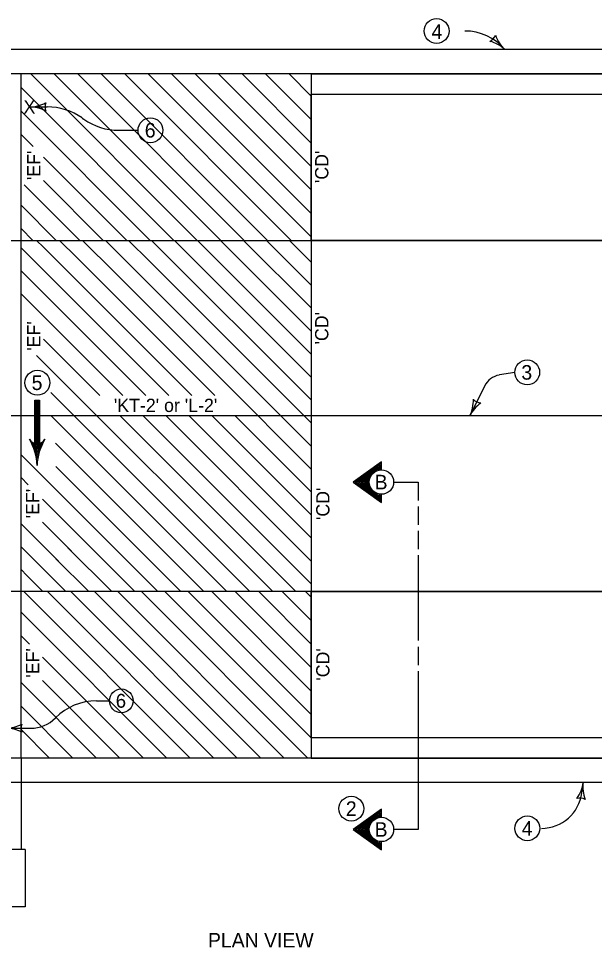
# Model space of a CAD drawing. Extents: x 10045 to 81668, y 6370 to 11018.
# Drawn here: x 10888 to 11617, y 6370 to 7544 of the extents above; entities that cross this region are included whole.
import ezdxf

# ---------------------------------------------------------------- set-up
doc = ezdxf.new("R2010")
doc.units = 0
for name, color, linetype in [('Alignment', 7, 'Continuous'), ('Default', 7, 'Continuous'), ('dsnStdLineWork', 7, 'Continuous')]:
    doc.layers.add(name, color=color, linetype=linetype)

msp = doc.modelspace()

# ---------------------------------------------------------------- linework, layer by layer
at = {"layer": 'Alignment'}
for p, q in [((11515.8, 7097), (11496.3, 7093.7)), ((11515.8, 7097), (11496.3, 7093.7)), ((11477.5, 7079.7), (11458.8, 7041.9)), ((11477.5, 7079.7), (11458.8, 7041.9)), ((10898.5, 6840.3), (10891.3, 6847.6)), ((10898.5, 6840.3), (10891.3, 6847.6)), ((12067.5, 6819.8), (10703.2, 6819.8)), ((12067.5, 6819.8), (10703.2, 6819.8)), ((11393.4, 6719.3), (11393.4, 6519.1)), ((11393.4, 6719.3), (11393.4, 6519.1)), ((10986.8, 6681.7), (11003.1, 6681.7)), ((10986.8, 6681.7), (11003.1, 6681.7)), ((10872.2, 6647.1), (10903.5, 6647.1)), ((10872.2, 6647.1), (10903.5, 6647.1)), ((11600.6, 6565.4), (11602.2, 6578.5)), ((11600.6, 6565.4), (11602.2, 6578.5))]:
    msp.add_line(p, q, dxfattribs=at)
for points in [[(11362.6, 6958.3), (11393.4, 6958.3), (11393.4, 6935.2)], [(11362.6, 6958.3), (11393.4, 6958.3), (11393.4, 6935.2)], [(11393.4, 6927.5), (11393.4, 6904.4)], [(11393.4, 6927.5), (11393.4, 6904.4)], [(11393.4, 6896.7), (11393.4, 6873.5)], [(11393.4, 6896.7), (11393.4, 6873.5)], [(11393.4, 6865.8), (11393.4, 6757.9)], [(11393.4, 6865.8), (11393.4, 6757.9)], [(11393.4, 6750.2), (11393.4, 6727)], [(11393.4, 6750.2), (11393.4, 6727)], [(11393.4, 6530.5), (11393.4, 6519.1), (11362.6, 6519.1)], [(11393.4, 6530.5), (11393.4, 6519.1), (11362.6, 6519.1)]]:
    msp.add_lwpolyline(points, dxfattribs=at)
for centre, radius, start, end in [((11452.5, 7461.8), 66.8, 40.5607, 90), ((11452.5, 7461.8), 66.8, 40.5607, 90), ((11500.5, 7068.3), 25.7, 99.5323, 153.7542), ((11500.5, 7068.3), 25.7, 99.5323, 153.7542), ((10986.8, 6608.3), 73.4, 90, 135), ((10986.8, 6608.3), 73.4, 90, 135), ((10903.5, 6691.2), 44.1, 270, 315), ((10903.5, 6691.2), 44.1, 270, 315), ((11549.6, 6571.9), 51.4, 270, 352.7713), ((11549.6, 6571.9), 51.4, 270, 352.7713)]:
    msp.add_arc(centre, radius, start, end, dxfattribs=at)
at = {"layer": 'Default'}
msp.add_line((11628.3, 7474.4), (10703.2, 7474.4), dxfattribs=at)
msp.add_line((11628.3, 7474.4), (10703.2, 7474.4), dxfattribs=at)
at = {"layer": 'dsnStdLineWork'}
for p, q in [((11591.3, 7505.2), (10703.2, 7505.2)), ((11591.3, 7505.2), (10703.2, 7505.2)), ((12004.1, 7505.2), (11591.3, 7505.2)), ((12004.1, 7505.2), (11591.3, 7505.2)), ((10891.3, 7263.9), (10891.3, 7474.4)), ((10891.3, 7263.9), (10891.3, 7474.4)), ((11114.1, 7263.9), (10903.6, 7474.4)), ((11114.1, 7263.9), (10903.6, 7474.4)), ((11143.8, 7263.9), (10933.3, 7474.4)), ((11143.8, 7263.9), (10933.3, 7474.4)), ((11173.5, 7263.9), (10963, 7474.4)), ((11173.5, 7263.9), (10963, 7474.4)), ((11203.2, 7263.9), (10992.7, 7474.4)), ((11203.2, 7263.9), (10992.7, 7474.4)), ((11232.9, 7263.9), (11022.4, 7474.4)), ((11232.9, 7263.9), (11022.4, 7474.4)), ((11258.2, 7268.2), (11052.1, 7474.4)), ((11258.2, 7268.2), (11052.1, 7474.4)), ((11258.2, 7297.9), (11081.8, 7474.4)), ((11258.2, 7297.9), (11081.8, 7474.4)), ((11258.2, 7327.6), (11111.5, 7474.4)), ((11258.2, 7327.6), (11111.5, 7474.4)), ((11258.2, 7357.3), (11141.2, 7474.4)), ((11258.2, 7357.3), (11141.2, 7474.4)), ((11258.2, 7387), (11170.9, 7474.4)), ((11258.2, 7387), (11170.9, 7474.4)), ((11258.2, 7416.7), (11200.6, 7474.4)), ((11258.2, 7416.7), (11200.6, 7474.4)), ((11258.2, 7446.4), (11230.3, 7474.4)), ((11258.2, 7446.4), (11230.3, 7474.4)), ((11628.3, 7474.4), (11258.2, 7474.4)), ((11258.2, 7474.4), (11628.3, 7474.4)), ((11258.2, 7474.4), (11258.2, 6819.8)), ((11628.3, 7474.4), (11258.2, 7474.4)), ((11258.2, 7474.4), (11628.3, 7474.4)), ((11258.2, 7474.4), (11258.2, 6819.8)), ((11084.4, 7263.9), (10891.3, 7457)), ((11084.4, 7263.9), (10891.3, 7457)), ((10891.3, 7263.9), (10891.3, 7448.9)), ((10891.3, 7263.9), (10891.3, 7448.9)), ((11258.2, 7263.9), (11258.2, 7448.9)), ((11258.2, 7263.9), (11258.2, 7448.9)), ((11258.2, 7448.9), (11628.3, 7448.9)), ((11258.2, 7263.9), (11258.2, 7448.9)), ((11258.2, 7263.9), (11258.2, 7448.9)), ((11258.2, 7448.9), (11628.3, 7448.9)), ((11054.7, 7263.9), (10891.3, 7427.3)), ((11054.7, 7263.9), (10891.3, 7427.3)), ((10901.6, 7432.6), (10924.3, 7432.6)), ((10901.6, 7432.6), (10924.3, 7432.6)), ((10968.5, 7418.6), (10970.8, 7417)), ((10968.5, 7418.6), (10970.8, 7417)), ((11015, 7403.1), (11039.2, 7403.1)), ((11015, 7403.1), (11039.2, 7403.1)), ((10906.5, 7382.4), (10891.3, 7397.6)), ((10906.5, 7382.4), (10891.3, 7397.6)), ((11025, 7263.9), (10919.7, 7369.2)), ((11025, 7263.9), (10919.7, 7369.2)), ((10965.6, 7263.9), (10895.2, 7334.2)), ((10965.6, 7263.9), (10895.2, 7334.2)), ((10995.3, 7263.9), (10919.7, 7339.5)), ((10995.3, 7263.9), (10919.7, 7339.5)), ((10935.9, 7263.9), (10891.3, 7308.5)), ((10935.9, 7263.9), (10891.3, 7308.5)), ((10906.2, 7263.9), (10891.3, 7278.8)), ((10906.2, 7263.9), (10891.3, 7278.8)), ((10703.2, 7263.9), (12114.2, 7263.9)), ((10703.2, 7263.9), (12114.2, 7263.9)), ((10891.3, 6819.8), (10891.3, 7263.9)), ((10891.3, 6819.8), (10891.3, 7263.9)), ((10919.6, 7255.4), (10911, 7263.9)), ((10919.6, 7255.4), (10911, 7263.9)), ((10961.9, 7242.1), (10940.1, 7263.9)), ((10961.9, 7242.1), (10940.1, 7263.9)), ((11010.3, 7222.8), (10969.2, 7263.9)), ((11010.3, 7222.8), (10969.2, 7263.9)), ((11036.2, 7225.9), (10998.3, 7263.9)), ((11036.2, 7225.9), (10998.3, 7263.9)), ((11053.6, 7237.6), (11027.3, 7263.9)), ((11053.6, 7237.6), (11027.3, 7263.9)), ((11258.2, 7062.1), (11056.4, 7263.9)), ((11258.2, 7062.1), (11056.4, 7263.9)), ((11258.2, 7091.1), (11085.5, 7263.9)), ((11258.2, 7091.1), (11085.5, 7263.9)), ((11258.2, 7120.2), (11114.6, 7263.9)), ((11258.2, 7120.2), (11114.6, 7263.9)), ((11258.2, 7149.3), (11143.6, 7263.9)), ((11258.2, 7149.3), (11143.6, 7263.9)), ((11258.2, 7178.4), (11172.7, 7263.9)), ((11258.2, 7178.4), (11172.7, 7263.9)), ((11258.2, 7207.4), (11201.8, 7263.9)), ((11258.2, 7207.4), (11201.8, 7263.9)), ((11258.2, 7236.5), (11230.9, 7263.9)), ((11258.2, 7236.5), (11230.9, 7263.9)), ((11628.3, 7263.9), (11258.2, 7263.9)), ((11258.2, 7263.9), (11258.2, 6819.8)), ((11628.3, 7263.9), (11258.2, 7263.9)), ((11628.3, 7263.9), (11258.2, 7263.9)), ((11258.2, 7263.9), (11258.2, 6819.8)), ((11628.3, 7263.9), (11258.2, 7263.9)), ((11078.2, 7067.7), (10891.3, 7254.6)), ((11078.2, 7067.7), (10891.3, 7254.6)), ((11107.2, 7067.7), (10919.6, 7255.4)), ((11107.2, 7067.7), (10919.6, 7255.4)), ((11136.3, 7067.7), (10961.9, 7242.1)), ((11136.3, 7067.7), (10961.9, 7242.1)), ((11258.2, 7033), (11053.6, 7237.6)), ((11258.2, 7033), (11053.6, 7237.6)), ((11049.1, 7067.7), (10891.3, 7225.5)), ((11049.1, 7067.7), (10891.3, 7225.5)), ((11010.3, 7222.8), (11017.1, 7216)), ((11144.7, 7088.4), (11010.3, 7222.8)), ((11010.3, 7222.8), (11017.1, 7216)), ((11144.7, 7088.4), (11010.3, 7222.8)), ((11258.2, 7003.9), (11036.2, 7225.9)), ((11258.2, 7003.9), (11036.2, 7225.9)), ((11020, 7067.7), (10891.3, 7196.4)), ((11020, 7067.7), (10891.3, 7196.4)), ((11258.7, 7154), (11258.2, 7154.4)), ((11258.7, 7154), (11258.2, 7154.4)), ((10990.9, 7067.7), (10919.7, 7138.9)), ((10990.9, 7067.7), (10919.7, 7138.9)), ((11209.8, 6819.8), (10911, 7118.5)), ((11209.8, 6819.8), (10911, 7118.5)), ((11258.2, 6974.8), (11144.7, 7088.4)), ((11258.2, 6974.8), (11144.7, 7088.4)), ((11180.7, 6819.8), (10929, 7071.5)), ((11180.7, 6819.8), (10929, 7071.5)), ((10911.7, 7007.2), (10911.7, 7061.7)), ((10911.7, 7007.2), (10911.7, 7061.7)), ((11628.3, 7041.9), (10112, 7041.9)), ((11628.3, 7041.9), (10112, 7041.9)), ((11151.6, 6819.8), (10929.6, 7041.9)), ((11151.6, 6819.8), (10929.6, 7041.9)), ((11169.4, 6889.3), (11016.8, 7041.9)), ((11169.4, 6889.3), (11016.8, 7041.9)), ((11183.9, 6903.8), (11045.9, 7041.9)), ((11183.9, 6903.8), (11045.9, 7041.9)), ((11258.2, 6858.5), (11074.9, 7041.9)), ((11258.2, 6858.5), (11074.9, 7041.9)), ((11258.2, 6887.6), (11104, 7041.9)), ((11258.2, 6887.6), (11104, 7041.9)), ((11258.2, 6916.7), (11133.1, 7041.9)), ((11258.2, 6916.7), (11133.1, 7041.9)), ((11258.2, 6945.8), (11162.2, 7041.9)), ((11258.2, 6945.8), (11162.2, 7041.9)), ((10908.4, 7007.3), (10908.4, 7007.3)), ((10908.4, 7007.3), (10908.4, 7007.3)), ((10914.7, 7007.3), (10914.7, 7007.3)), ((10914.7, 7007.3), (10914.7, 7007.3)), ((11122.5, 6819.8), (10935, 7007.3)), ((11122.5, 6819.8), (10935, 7007.3)), ((11006.1, 6878.1), (10891.3, 6992.9)), ((11006.1, 6878.1), (10891.3, 6992.9)), ((11022.6, 6890.7), (10935.4, 6977.8)), ((11022.6, 6890.7), (10935.4, 6977.8)), ((10900.4, 6954.8), (10891.3, 6963.9)), ((10900.4, 6954.8), (10891.3, 6963.9)), ((10977.6, 6877.5), (10918.4, 6936.7)), ((10977.6, 6877.5), (10918.4, 6936.7)), ((10938.7, 6858.3), (10891.3, 6905.7)), ((10938.7, 6858.3), (10891.3, 6905.7)), ((10955.1, 6870.9), (10918.4, 6907.6)), ((10955.1, 6870.9), (10918.4, 6907.6)), ((11093.5, 6819.8), (11018.4, 6894.8)), ((11093.5, 6819.8), (11018.4, 6894.8)), ((11258.2, 6829.5), (11183.9, 6903.8)), ((11258.2, 6829.5), (11183.9, 6903.8)), ((11238.8, 6819.8), (11169.4, 6889.3)), ((11238.8, 6819.8), (11169.4, 6889.3)), ((10923.2, 6844.7), (10891.3, 6876.6)), ((10923.2, 6844.7), (10891.3, 6876.6)), ((11006.2, 6819.8), (10950.7, 6875.3)), ((11006.2, 6819.8), (10950.7, 6875.3)), ((11035.3, 6819.8), (10977.6, 6877.5)), ((11035.3, 6819.8), (10977.6, 6877.5)), ((11064.4, 6819.8), (11006.1, 6878.1)), ((11064.4, 6819.8), (11006.1, 6878.1)), ((10977.2, 6819.8), (10935.5, 6861.4)), ((10977.2, 6819.8), (10935.5, 6861.4)), ((10919, 6819.8), (10898.5, 6840.3)), ((10919, 6819.8), (10898.5, 6840.3)), ((10948.1, 6819.8), (10923.2, 6844.7)), ((10948.1, 6819.8), (10923.2, 6844.7)), ((10891.3, 6609.3), (10891.3, 6819.8)), ((10891.3, 6609.3), (10891.3, 6819.8)), ((11105.4, 6609.3), (10895, 6819.8)), ((11105.4, 6609.3), (10895, 6819.8)), ((11135.1, 6609.3), (10924.7, 6819.8)), ((11135.1, 6609.3), (10924.7, 6819.8)), ((11164.8, 6609.3), (10954.4, 6819.8)), ((11164.8, 6609.3), (10954.4, 6819.8)), ((11194.5, 6609.3), (10984.1, 6819.8)), ((11194.5, 6609.3), (10984.1, 6819.8)), ((11224.2, 6609.3), (11013.8, 6819.8)), ((11224.2, 6609.3), (11013.8, 6819.8)), ((11253.9, 6609.3), (11043.5, 6819.8)), ((11253.9, 6609.3), (11043.5, 6819.8)), ((11258.2, 6634.8), (11073.1, 6819.8)), ((11258.2, 6634.8), (11073.1, 6819.8)), ((11258.2, 6664.4), (11102.8, 6819.8)), ((11258.2, 6664.4), (11102.8, 6819.8)), ((11258.2, 6694.1), (11132.5, 6819.8)), ((11258.2, 6694.1), (11132.5, 6819.8)), ((11258.2, 6723.8), (11162.2, 6819.8)), ((11258.2, 6723.8), (11162.2, 6819.8)), ((11258.2, 6753.5), (11191.9, 6819.8)), ((11258.2, 6753.5), (11191.9, 6819.8)), ((11258.2, 6783.2), (11221.6, 6819.8)), ((11258.2, 6783.2), (11221.6, 6819.8)), ((11258.2, 6812.9), (11251.3, 6819.8)), ((11258.2, 6812.9), (11251.3, 6819.8)), ((11258.2, 6819.8), (11258.2, 6634.8)), ((11258.2, 6819.8), (11258.2, 6634.8)), ((11258.2, 6819.8), (11258.2, 6609.3)), ((11258.2, 6634.8), (11258.2, 6819.8)), ((11258.2, 6819.8), (11628.3, 6819.8)), ((11258.2, 6819.8), (11628.3, 6819.8)), ((11258.2, 6819.8), (11258.2, 6634.8)), ((11258.2, 6819.8), (11258.2, 6634.8)), ((11258.2, 6819.8), (11258.2, 6609.3)), ((11258.2, 6634.8), (11258.2, 6819.8)), ((11258.2, 6819.8), (11628.3, 6819.8)), ((11258.2, 6819.8), (11628.3, 6819.8)), ((11075.7, 6609.3), (10891.3, 6793.8)), ((11075.7, 6609.3), (10891.3, 6793.8)), ((10902.1, 6753.3), (10891.3, 6764.1)), ((10902.1, 6753.3), (10891.3, 6764.1)), ((11046, 6609.3), (10918.4, 6736.9)), ((11046, 6609.3), (10918.4, 6736.9)), ((11016.3, 6609.3), (10918.4, 6707.3)), ((11016.3, 6609.3), (10918.4, 6707.3)), ((10986.6, 6609.3), (10891.3, 6704.7)), ((10986.6, 6609.3), (10891.3, 6704.7)), ((10956.9, 6609.3), (10891.3, 6675)), ((10956.9, 6609.3), (10891.3, 6675)), ((10927.2, 6609.3), (10891.3, 6645.3)), ((10927.2, 6609.3), (10891.3, 6645.3)), ((11628.3, 6634.8), (11258.2, 6634.8)), ((11628.3, 6634.8), (11258.2, 6634.8)), ((11628.3, 6609.3), (10703.2, 6609.3)), ((11628.3, 6609.3), (10703.2, 6609.3)), ((10891.3, 6609.3), (10891.3, 6493.6)), ((10891.3, 6609.3), (10891.3, 6493.6)), ((11591.3, 6578.5), (10703.2, 6578.5)), ((11591.3, 6578.5), (10703.2, 6578.5)), ((11918.6, 6578.5), (11591.3, 6578.5)), ((11918.6, 6578.5), (11591.3, 6578.5)), ((10896.4, 6493.6), (10880, 6493.6)), ((10896.4, 6493.6), (10880, 6493.6)), ((10896.4, 6493.6), (10896.4, 6421.2)), ((10896.4, 6493.6), (10896.4, 6421.2)), ((10896.4, 6421.2), (10880, 6421.2)), ((10896.4, 6421.2), (10880, 6421.2))]:
    msp.add_line(p, q, dxfattribs=at)
for points in [[(11628.3, 7456.6), (11628.3, 7456.6), (11628.3, 7474.4), (11258.2, 7474.4), (11258.2, 7448.9), (11628.3, 7448.9)], [(11628.3, 7456.6), (11628.3, 7456.6), (11628.3, 7474.4), (11258.2, 7474.4), (11258.2, 7448.9), (11628.3, 7448.9)], [(11628.3, 6627.1), (11628.3, 6634.8), (11258.2, 6634.8), (11258.2, 6609.3), (11628.3, 6609.3), (11628.3, 6627.1)], [(11628.3, 6627.1), (11628.3, 6634.8), (11258.2, 6634.8), (11258.2, 6609.3), (11628.3, 6609.3), (11628.3, 6627.1)]]:
    msp.add_lwpolyline(points, close=True, dxfattribs=at)
for points in [[(10891.3, 7263.9), (10891.3, 7263.9)], [(10891.3, 7263.9), (10891.3, 7263.9)], [(10908.6, 7007.3), (10908.6, 7061.7), (10914.7, 7061.7), (10914.7, 7007.3), (10909.5, 7007.5), (10909.3, 7061), (10914.2, 7060.9), (10914, 7008.5), (10910.3, 7008.3), (10910.1, 7060.2), (10913.3, 7060.1), (10913.3, 7009.2), (10911, 7009), (10910.8, 7059.6), (10912.6, 7059.6), (10912.5, 7009.8)], [(10908.6, 7007.3), (10908.6, 7061.7), (10914.7, 7061.7), (10914.7, 7007.3), (10909.5, 7007.5), (10909.3, 7061), (10914.2, 7060.9), (10914, 7008.5), (10910.3, 7008.3), (10910.1, 7060.2), (10913.3, 7060.1), (10913.3, 7009.2), (10911, 7009), (10910.8, 7059.6), (10912.6, 7059.6), (10912.5, 7009.8)], [(10904.6, 7008.7), (10908.2, 7006.4), (10913.6, 7006.2), (10918.3, 7008.1), (10915, 7000.1), (10912.3, 6990.7), (10911.6, 6988), (10910.3, 6994.8), (10906.9, 7004.7), (10905.3, 7007.7), (10916.8, 7006.6), (10911.8, 6992.1), (10907.6, 7006.2), (10915.5, 7005.7), (10911.8, 6995.7), (10909.5, 7004.9), (10914.1, 7005.3), (10912, 6998.9), (10910.7, 7003.8), (10912.9, 7004), (10912.2, 7001.7)], [(10904.6, 7008.7), (10908.2, 7006.4), (10913.6, 7006.2), (10918.3, 7008.1), (10915, 7000.1), (10912.3, 6990.7), (10911.6, 6988), (10910.3, 6994.8), (10906.9, 7004.7), (10905.3, 7007.7), (10916.8, 7006.6), (10911.8, 6992.1), (10907.6, 7006.2), (10915.5, 7005.7), (10911.8, 6995.7), (10909.5, 7004.9), (10914.1, 7005.3), (10912, 6998.9), (10910.7, 7003.8), (10912.9, 7004), (10912.2, 7001.7)], [(11347.2, 6973.7), (11347.2, 6984), (11311.2, 6958.3), (11347.2, 6932.6), (11347.2, 6942.9)], [(11347.2, 6973.7), (11347.2, 6984), (11311.2, 6958.3), (11347.2, 6932.6), (11347.2, 6942.9)], [(11346.2, 6941.9), (11346.3, 6934.5), (11313.1, 6958.3), (11346.3, 6982.4), (11346.1, 6974.5), (11344.7, 6974.1), (11345.3, 6979.8), (11315.3, 6958.3), (11345.3, 6936.6), (11344.9, 6942.1), (11343.9, 6942.3), (11343.9, 6938.6), (11317.3, 6958.4), (11344, 6977.2), (11343.5, 6974), (11342.3, 6973.7), (11342.5, 6974.8), (11319.6, 6958.1), (11342.8, 6940.6), (11341.7, 6942.5), (11321.6, 6958), (11333.9, 6967.7), (11333.2, 6965.9), (11323.7, 6957.9), (11332.8, 6950.9), (11332, 6952.8), (11325.6, 6957.6), (11332, 6963.1), (11331.4, 6960.7), (11327.3, 6957.6), (11331.4, 6954.3), (11331.2, 6956), (11328.8, 6957.5), (11331.1, 6958.9), (11331, 6957.4), (11330.2, 6957.5)], [(11346.2, 6941.9), (11346.3, 6934.5), (11313.1, 6958.3), (11346.3, 6982.4), (11346.1, 6974.5), (11344.7, 6974.1), (11345.3, 6979.8), (11315.3, 6958.3), (11345.3, 6936.6), (11344.9, 6942.1), (11343.9, 6942.3), (11343.9, 6938.6), (11317.3, 6958.4), (11344, 6977.2), (11343.5, 6974), (11342.3, 6973.7), (11342.5, 6974.8), (11319.6, 6958.1), (11342.8, 6940.6), (11341.7, 6942.5), (11321.6, 6958), (11333.9, 6967.7), (11333.2, 6965.9), (11323.7, 6957.9), (11332.8, 6950.9), (11332, 6952.8), (11325.6, 6957.6), (11332, 6963.1), (11331.4, 6960.7), (11327.3, 6957.6), (11331.4, 6954.3), (11331.2, 6956), (11328.8, 6957.5), (11331.1, 6958.9), (11331, 6957.4), (11330.2, 6957.5)], [(10891.3, 6819.8), (10891.3, 6819.8)], [(10891.3, 6819.8), (10891.3, 6819.8)], [(11347.2, 6534.5), (11347.2, 6544.8), (11311.2, 6519.1), (11347.2, 6493.4), (11347.2, 6503.7)], [(11347.2, 6534.5), (11347.2, 6544.8), (11311.2, 6519.1), (11347.2, 6493.4), (11347.2, 6503.7)], [(11346.2, 6502.7), (11346.3, 6495.2), (11313.1, 6519.1), (11346.3, 6543.2), (11346.1, 6535.3), (11344.7, 6534.9), (11345.3, 6540.6), (11315.3, 6519.1), (11345.3, 6497.3), (11344.9, 6502.8), (11343.9, 6503.1), (11343.9, 6499.4), (11317.3, 6519.2), (11344, 6538), (11343.5, 6534.8), (11342.3, 6534.5), (11342.5, 6535.6), (11319.6, 6518.9), (11342.8, 6501.4), (11341.7, 6503.3), (11321.6, 6518.7), (11333.9, 6528.5), (11333.2, 6526.7), (11323.7, 6518.7), (11332.8, 6511.7), (11332, 6513.5), (11325.6, 6518.4), (11332, 6523.9), (11331.4, 6521.5), (11327.3, 6518.4), (11331.4, 6515.1), (11331.2, 6516.8), (11328.8, 6518.3), (11331.1, 6519.7), (11331, 6518.2), (11330.2, 6518.3)], [(11346.2, 6502.7), (11346.3, 6495.2), (11313.1, 6519.1), (11346.3, 6543.2), (11346.1, 6535.3), (11344.7, 6534.9), (11345.3, 6540.6), (11315.3, 6519.1), (11345.3, 6497.3), (11344.9, 6502.8), (11343.9, 6503.1), (11343.9, 6499.4), (11317.3, 6519.2), (11344, 6538), (11343.5, 6534.8), (11342.3, 6534.5), (11342.5, 6535.6), (11319.6, 6518.9), (11342.8, 6501.4), (11341.7, 6503.3), (11321.6, 6518.7), (11333.9, 6528.5), (11333.2, 6526.7), (11323.7, 6518.7), (11332.8, 6511.7), (11332, 6513.5), (11325.6, 6518.4), (11332, 6523.9), (11331.4, 6521.5), (11327.3, 6518.4), (11331.4, 6515.1), (11331.2, 6516.8), (11328.8, 6518.3), (11331.1, 6519.7), (11331, 6518.2), (11330.2, 6518.3)]]:
    msp.add_lwpolyline(points, dxfattribs=at)
for centre, radius in [((11416.9, 7528.6), 15.7), ((11416.9, 7528.6), 15.7), ((11055, 7403.1), 15.7), ((11055, 7403.1), 15.7), ((11531.5, 7097), 15.7), ((11531.5, 7097), 15.7), ((10912, 7083.9), 15.7), ((10912, 7083.9), 15.7), ((11347.2, 6958.3), 15.4), ((11347.2, 6958.3), 15.4), ((11018.1, 6681.7), 15), ((11018.1, 6681.7), 15), ((11309, 6545.4), 15.7), ((11309, 6545.4), 15.7), ((11347.2, 6519.1), 15.4), ((11347.2, 6519.1), 15.4), ((11531.7, 6520.5), 15.7), ((11531.7, 6520.5), 15.7)]:
    msp.add_circle(centre, radius, dxfattribs=at)
for centre, radius, start, end in [((11475.9, 7530.4), 17.1, 299.4947, 334.9614), ((11475.9, 7530.4), 17.1, 299.4947, 334.9614), ((11533.4, 7537.8), 44.4, 199.1556, 227.2281), ((11533.4, 7537.8), 44.4, 199.1556, 227.2281), ((11473.1, 7472.6), 44.4, 47.2281, 75.3006), ((11473.1, 7472.6), 44.4, 47.2281, 75.3006), ((10901.5, 7477), 44.4, 270, 298.0725), ((10901.5, 7477), 44.4, 270, 298.0725), ((10901.6, 7477), 44.4, 270, 298.0725), ((10901.6, 7477), 44.4, 270, 298.0725), ((10938.8, 7432.6), 17.1, 162.2666, 197.7334), ((10938.8, 7432.6), 17.1, 162.2666, 197.7334), ((10938.8, 7432.6), 17.1, 162.2666, 197.7334), ((10938.8, 7432.6), 17.1, 162.2666, 197.7334), ((10901.5, 7388.2), 44.4, 61.9275, 90), ((10901.5, 7388.2), 44.4, 61.9275, 90), ((10901.6, 7388.2), 44.4, 61.9275, 90), ((10901.6, 7388.2), 44.4, 61.9275, 90), ((10924.3, 7355.5), 77.1, 55.0007, 90), ((10924.3, 7355.5), 77.1, 55.0007, 90), ((11015, 7480.2), 77.1, 235.0001, 270), ((11015, 7480.2), 77.1, 235.0001, 270), ((11419, 7061.5), 44.4, 333.7545, 1.8269), ((11419, 7061.5), 44.4, 333.7545, 1.8269), ((11498.6, 7022.2), 44.4, 125.682, 153.7545), ((11498.6, 7022.2), 44.4, 125.682, 153.7545), ((11475.3, 7075.2), 17.1, 226.0211, 261.4878), ((11475.3, 7075.2), 17.1, 226.0211, 261.4878), ((10911.7, 7018.5), 11.6, 211.7147, 328.2853), ((10845.4, 6977.5), 66.3, 1.6842, 31.7143), ((10911.7, 7018.5), 11.6, 211.7147, 328.2853), ((10845.4, 6977.5), 66.3, 1.6842, 31.7143), ((10977.9, 6977.5), 66.3, 148.2857, 178.3158), ((10977.9, 6977.5), 66.3, 148.2857, 178.3158), ((10872.2, 6689.4), 42.3, 270, 298.0725), ((10872.2, 6689.4), 42.3, 270, 298.0725), ((10872.2, 6604.8), 42.3, 61.9275, 90), ((10872.2, 6604.8), 42.3, 61.9275, 90), ((10907.7, 6647.1), 16.3, 162.2666, 197.7334), ((10907.7, 6647.1), 16.3, 162.2666, 197.7334), ((11558.2, 6584.1), 44.4, 324.6988, 352.7713), ((11558.2, 6584.1), 44.4, 324.6988, 352.7713), ((11646.3, 6572.9), 44.4, 172.7713, 200.8438), ((11646.3, 6572.9), 44.4, 172.7713, 200.8438), ((11597.5, 6541.6), 17.1, 65.0379, 100.5046), ((11597.5, 6541.6), 17.1, 65.0379, 100.5046)]:
    msp.add_arc(centre, radius, start, end, dxfattribs=at)

# ---------------------------------------------------------------- texts
at = {"layer": 'Alignment'}
for s, height, p in [('4', 18.4, (11410.5, 7518.7)), ('4', 18.4, (11410.5, 7518.7)), ('X', 16.8, (10894.4, 7424.2)), ('X', 16.8, (10894.4, 7424.2)), ('6', 18.4, (11047.8, 7393.9)), ('6', 18.4, (11047.8, 7393.9)), ('3', 18.4, (11524.1, 7087.8)), ('3', 18.4, (11524.1, 7087.8)), ('5', 18.4, (10904.7, 7074.7)), ('5', 18.4, (10904.7, 7074.7)), ("'KT-2' or 'L-2'", 16.8, (11008.7, 7046.9)), ("'KT-2' or 'L-2'", 16.8, (11008.7, 7046.9)), ('B', 18.4, (11338.5, 6949.1)), ('B', 18.4, (11338.5, 6949.1)), ('6', 17.5, (11011.1, 6673)), ('6', 17.5, (11011.1, 6673)), ('2', 18.4, (11302.1, 6536.2)), ('2', 18.4, (11302.1, 6536.2)), ('4', 18.4, (11524.6, 6511.3)), ('4', 18.4, (11524.6, 6511.3)), ('B', 18.4, (11338.5, 6509.9)), ('B', 18.4, (11338.5, 6509.9)), ('PLAN VIEW', 18.37, (11127.7, 6369.9)), ('PLAN VIEW', 18.37, (11127.7, 6369.9))]:
    msp.add_text(s, height=height, dxfattribs=at).set_placement(p)
for s, p in [("'EF'", (10915.7, 7340.1)), ("'EF'", (10915.7, 7340.1)), ("'CD'", (11280, 7336.3)), ("'CD'", (11280, 7336.3)), ("'CD'", (11280, 7132.3)), ("'CD'", (11280, 7132.3)), ("'EF'", (10915.7, 7124.4)), ("'EF'", (10915.7, 7124.4)), ("'EF'", (10914.4, 6912.5)), ("'EF'", (10914.4, 6912.5)), ("'CD'", (11281.4, 6910.3)), ("'CD'", (11281.4, 6910.3)), ("'EF'", (10914.4, 6711)), ("'EF'", (10914.4, 6711)), ("'CD'", (11281.4, 6707.2)), ("'CD'", (11281.4, 6707.2))]:
    msp.add_text(s, height=16.8, rotation=90, dxfattribs=at).set_placement(p)

doc.saveas('drawing.dxf')
